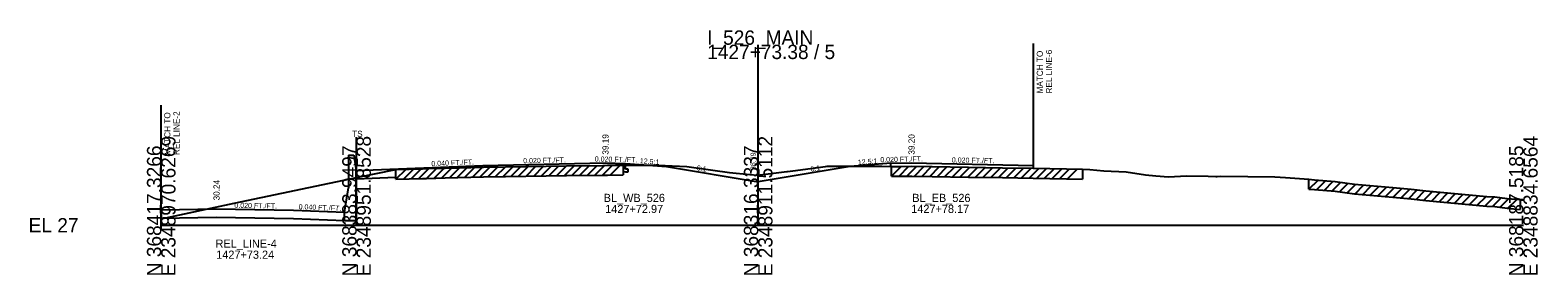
# Model space of a CAD drawing. Extents: x -170 to 2527928, y -10 to 1619750.
# Drawn here: x 3974.3 to 4269.9, y 5490.3 to 5538.2 of the extents above; entities that cross this region are included whole.
import ezdxf

# ---------------------------------------------------------------- set-up
doc = ezdxf.new("R2010")
doc.units = 0
for name, color, linetype in [('RD_GPK_XS_Cell', 7, 'Continuous'), ('RD_PD_NOISE-WALL-GM', 7, 'Continuous'), ('RD_XS_Base', 7, 'Continuous'), ('RD_XS_EarthShd', 7, 'Continuous'), ('RD_XS_ExGround', 7, 'Continuous'), ('RD_XS_ExPaveRet', 7, 'Continuous'), ('RD_XS_MatchLine', 7, 'Continuous'), ('RD_XS_Pave', 7, 'Continuous'), ('RD_XS_PaveShd', 7, 'Continuous'), ('RD_XS_TieSlope', 7, 'Continuous'), ('RD_XS_TX_Elev_EX', 7, 'Continuous'), ('RD_XS_TX_Slope', 7, 'Continuous'), ('RD_XS_TX_Station', 7, 'Continuous')]:
    doc.layers.add(name, color=color, linetype=linetype)

msp = doc.modelspace()

# ---------------------------------------------------------------- linework, layer by layer
at = {"layer": 'RD_GPK_XS_Cell'}
for p, q in [((4117.03, 5500), (4117.03, 5535.32)), ((4000, 5500), (4038.29, 5500)), ((4038.29, 5500), (4117.03, 5500)), ((4117.03, 5500), (4267.03, 5500))]:
    msp.add_line(p, q, dxfattribs=at)
at = {"layer": 'RD_PD_NOISE-WALL-GM'}
for p, q in [((4036.73, 5513.72), (4037.73, 5513.72)), ((4036.73, 5513.72), (4036.73, 5507.35)), ((4037.73, 5513.72), (4038.21, 5510.72)), ((4038.21, 5500.9), (4038.21, 5510.72)), ((4035.96, 5502.54), (4036.73, 5507.35)), ((4035.96, 5500.9), (4035.96, 5502.54)), ((4035.96, 5500.9), (4038.29, 5500.9))]:
    msp.add_line(p, q, dxfattribs=at)
at = {"layer": 'RD_XS_Base'}
for p, q in [((4038.21, 5509.08), (4046.02, 5509.4)), ((4046.02, 5510.94), (4046.02, 5511.03)), ((4090.54, 5510.49), (4091.03, 5510.48)), ((4091.03, 5510.98), (4091.03, 5512.11)), ((4091.53, 5510.97), (4091.03, 5510.98)), ((4091.03, 5510.48), (4091.53, 5510.47)), ((4091.53, 5510.47), (4091.53, 5510.97)), ((4143.03, 5511.5), (4143.03, 5512.12)), ((4171.03, 5511.14), (4171.03, 5511.72)), ((4000, 5501.39), (4010.78, 5501.6)), ((4010.78, 5501.6), (4025.96, 5501.3)), ((4025.96, 5501.3), (4035.96, 5500.9))]:
    msp.add_line(p, q, dxfattribs=at)
at = {"layer": 'RD_XS_EarthShd'}
for p, q in [((4091.03, 5512.11), (4099.03, 5511.47)), ((4143.03, 5512.12), (4135.03, 5511.48))]:
    msp.add_line(p, q, dxfattribs=at)
at = {"layer": 'RD_XS_ExGround'}
msp.add_lwpolyline([(4000, 5501.24), (4014.33, 5504.31), (4038.29, 5509.32), (4046.02, 5510.94), (4051.25, 5511.06), (4052.01, 5511.08), (4055.67, 5511.19), (4063.19, 5511.39), (4067.46, 5511.46), (4075.49, 5511.58), (4079.43, 5511.63), (4086.55, 5511.72), (4087.52, 5511.74), (4090.54, 5511.77), (4097.39, 5511.77), (4100.17, 5511.65), (4103.02, 5511.5), (4104.4, 5511.31), (4111.41, 5510.3), (4115.38, 5509.93), (4116.88, 5509.77), (4122.63, 5510.51), (4122.76, 5510.53), (4123.85, 5510.67), (4130.24, 5511.5), (4130.53, 5511.53), (4141.24, 5511.57), (4143.15, 5511.5), (4144.73, 5511.52), (4147.14, 5511.54), (4151.11, 5511.47), (4158.23, 5511.34), (4164.94, 5511.24), (4170.93, 5511.14), (4177.49, 5511.03), (4180.58, 5510.97), (4182.03, 5510.88), (4184.8, 5510.66), (4189.17, 5510.47), (4192.98, 5509.89), (4194.95, 5509.65), (4197.44, 5509.5), (4200.99, 5509.66), (4205.22, 5509.61), (4206.76, 5509.54), (4207.01, 5509.53), (4207.75, 5509.59), (4218.28, 5509.45), (4220.38, 5509.32), (4225, 5508.99), (4226.06, 5508.91), (4230.17, 5508.57), (4233.93, 5508.04), (4241.45, 5507.39), (4245.02, 5507.06), (4247.91, 5506.76), (4259.84, 5505.64), (4261.47, 5505.56), (4263.88, 5505.26), (4266.39, 5505.01), (4266.59, 5504.99), (4266.89, 5504.97), (4267.03, 5504.95)], dxfattribs=at)
at = {"layer": 'RD_XS_ExPaveRet'}
for p, q in [((4046.02, 5509.02), (4047.99, 5510.98)), ((4046.02, 5509.02), (4046.02, 5510.94)), ((4047.52, 5509.05), (4049.49, 5511.02)), ((4049.02, 5509.09), (4050.99, 5511.05)), ((4050.52, 5509.13), (4052.49, 5511.1)), ((4052.02, 5509.16), (4054, 5511.14)), ((4053.52, 5509.21), (4055.5, 5511.18)), ((4055.02, 5509.25), (4057, 5511.22)), ((4055.67, 5509.27), (4063.19, 5509.48)), ((4056.52, 5509.29), (4058.5, 5511.26)), ((4058.02, 5509.33), (4060, 5511.31)), ((4059.52, 5509.38), (4061.5, 5511.35)), ((4061.02, 5509.42), (4063, 5511.39)), ((4062.52, 5509.46), (4064.48, 5511.41)), ((4063.19, 5509.48), (4067.46, 5509.54)), ((4064.02, 5509.49), (4065.97, 5511.44)), ((4065.52, 5509.51), (4067.47, 5511.46)), ((4067.02, 5509.53), (4068.97, 5511.48)), ((4067.46, 5509.54), (4075.49, 5509.67)), ((4068.52, 5509.56), (4070.47, 5511.5)), ((4070.02, 5509.58), (4071.97, 5511.53)), ((4071.52, 5509.6), (4073.47, 5511.55)), ((4073.02, 5509.63), (4074.97, 5511.58)), ((4074.52, 5509.65), (4076.47, 5511.59)), ((4075.49, 5509.67), (4079.43, 5509.71)), ((4076.02, 5509.67), (4077.96, 5511.61)), ((4077.52, 5509.69), (4079.46, 5511.63)), ((4079.02, 5509.7), (4080.97, 5511.65)), ((4079.43, 5509.71), (4086.55, 5509.81)), ((4080.52, 5509.72), (4082.47, 5511.67)), ((4082.02, 5509.74), (4083.97, 5511.69)), ((4083.52, 5509.76), (4085.47, 5511.71)), ((4085.02, 5509.78), (4086.97, 5511.73)), ((4086.52, 5509.8), (4088.47, 5511.75)), ((4086.55, 5509.81), (4087.52, 5509.82)), ((4087.52, 5509.82), (4090.54, 5509.86)), ((4088.02, 5509.82), (4089.97, 5511.77)), ((4090.54, 5511.77), (4090.54, 5509.86)), ((4143.15, 5509.58), (4145.08, 5511.52)), ((4143.15, 5509.58), (4143.15, 5511.5)), ((4143.15, 5509.58), (4144.73, 5509.6)), ((4144.65, 5509.6), (4146.58, 5511.53)), ((4144.73, 5509.6), (4147.14, 5509.62)), ((4146.15, 5509.61), (4148.06, 5511.52)), ((4147.14, 5509.62), (4151.11, 5509.55)), ((4147.65, 5509.61), (4149.53, 5511.5)), ((4149.15, 5509.59), (4151.03, 5511.47)), ((4150.65, 5509.56), (4152.53, 5511.44)), ((4151.11, 5509.55), (4158.23, 5509.42)), ((4152.15, 5509.53), (4154.03, 5511.42)), ((4153.65, 5509.51), (4155.53, 5511.39)), ((4155.15, 5509.48), (4157.03, 5511.36)), ((4156.65, 5509.45), (4158.53, 5511.34)), ((4158.15, 5509.43), (4160.04, 5511.31)), ((4158.23, 5509.42), (4164.94, 5509.32)), ((4159.65, 5509.4), (4161.54, 5511.29)), ((4161.15, 5509.38), (4163.04, 5511.27)), ((4162.65, 5509.36), (4164.54, 5511.24)), ((4164.15, 5509.33), (4166.04, 5511.22)), ((4164.94, 5509.32), (4170.93, 5509.23)), ((4165.65, 5509.31), (4167.54, 5511.2)), ((4167.15, 5509.28), (4169.04, 5511.17)), ((4168.65, 5509.26), (4170.54, 5511.15)), ((4170.15, 5509.24), (4172.04, 5511.12)), ((4171.65, 5509.21), (4173.53, 5511.1)), ((4173.15, 5509.19), (4175.03, 5511.07)), ((4174.65, 5509.16), (4176.53, 5511.04)), ((4176.15, 5509.13), (4178.03, 5511.02)), ((4177.65, 5509.11), (4179.53, 5510.99)), ((4180.58, 5510.97), (4180.58, 5509.05)), ((4046.02, 5509.02), (4051.25, 5509.14)), ((4051.25, 5509.14), (4052.01, 5509.16)), ((4052.01, 5509.16), (4055.67, 5509.27)), ((4170.93, 5509.23), (4177.49, 5509.11)), ((4177.49, 5509.11), (4180.58, 5509.05)), ((4225, 5507.07), (4225, 5508.99)), ((4225, 5507.07), (4226.78, 5508.85)), ((4225, 5507.07), (4226.06, 5506.99)), ((4226.06, 5506.99), (4230.17, 5506.65)), ((4226.5, 5506.95), (4228.27, 5508.72)), ((4228, 5506.83), (4229.77, 5508.6)), ((4229.5, 5506.7), (4231.22, 5508.42)), ((4230.17, 5506.65), (4233.93, 5506.12)), ((4231, 5506.53), (4232.68, 5508.21)), ((4232.5, 5506.32), (4234.19, 5508.01)), ((4234, 5506.11), (4235.77, 5507.88)), ((4235.5, 5505.98), (4237.27, 5507.75)), ((4237, 5505.86), (4238.77, 5507.62)), ((4238.5, 5505.73), (4240.27, 5507.49)), ((4240, 5505.6), (4241.77, 5507.36)), ((4241.5, 5505.47), (4243.26, 5507.23)), ((4243, 5505.33), (4244.76, 5507.09)), ((4244.5, 5505.19), (4246.24, 5506.93)), ((4246, 5505.04), (4247.73, 5506.78)), ((4247.5, 5504.88), (4249.25, 5506.63)), ((4249, 5504.74), (4250.75, 5506.49)), ((4250.5, 5504.6), (4252.25, 5506.35)), ((4233.93, 5506.12), (4241.45, 5505.48)), ((4241.45, 5505.48), (4245.02, 5505.15)), ((4245.02, 5505.15), (4247.91, 5504.84)), ((4247.91, 5504.84), (4259.84, 5503.73)), ((4252, 5504.46), (4253.75, 5506.21)), ((4253.5, 5504.32), (4255.25, 5506.07)), ((4255, 5504.18), (4256.75, 5505.93)), ((4256.5, 5504.04), (4258.25, 5505.79)), ((4258, 5503.9), (4259.75, 5505.65)), ((4259.5, 5503.76), (4261.31, 5505.57)), ((4259.84, 5503.73), (4261.47, 5503.64)), ((4261, 5503.67), (4262.74, 5505.4)), ((4261.47, 5503.64), (4263.88, 5503.34)), ((4262.5, 5503.51), (4264.21, 5505.22)), ((4264, 5503.33), (4265.74, 5505.07)), ((4266.39, 5505.01), (4266.39, 5503.09)), ((4263.88, 5503.34), (4266.39, 5503.09))]:
    msp.add_line(p, q, dxfattribs=at)
at = {"layer": 'RD_XS_MatchLine'}
for p, q in [((4171.03, 5511.14), (4171.03, 5535.55)), ((4000, 5499.09), (4000, 5523.5)), ((4038.29, 5500), (4038.29, 5517.22))]:
    msp.add_line(p, q, dxfattribs=at)
at = {"layer": 'RD_XS_Pave'}
for p, q in [((4063.03, 5511.71), (4087.03, 5512.19)), ((4147.03, 5512.2), (4171.03, 5511.72)), ((4010.78, 5503.24), (4025.96, 5502.94))]:
    msp.add_line(p, q, dxfattribs=at)
at = {"layer": 'RD_XS_PaveShd'}
for p, q in [((4038.21, 5510.72), (4063.03, 5511.71)), ((4087.03, 5512.19), (4091.03, 5512.11)), ((4143.03, 5512.12), (4147.03, 5512.2)), ((4000, 5503.02), (4010.78, 5503.24)), ((4000, 5503.02), (4000, 5501.24)), ((4025.96, 5502.94), (4035.96, 5502.54))]:
    msp.add_line(p, q, dxfattribs=at)
at = {"layer": 'RD_XS_TieSlope'}
for p in [(4099.03, 5511.47), (4135.03, 5511.48)]:
    msp.add_line(p, (4117.03, 5508.48), dxfattribs=at)

# ---------------------------------------------------------------- texts
at = {"layer": 'RD_GPK_XS_Cell'}
for s, p in [('I_526_MAIN', (4107.03, 5535.32)), ('1427+73.38 / 5', (4107.03, 5532.52)), ('EL 27', (3974, 5498.6))]:
    msp.add_text(s, height=2.8, dxfattribs=at).set_placement(p)
for s, p in [('N 368417.3266', (4000, 5490)), ('E 2348970.6269', (4002.8, 5490)), ('N 368383.9497', (4038.29, 5490)), ('E 2348951.8528', (4041.09, 5490)), ('N 368316.3337', (4117.03, 5490)), ('E 2348911.5112', (4119.83, 5490)), ('N 368187.5185', (4267.03, 5490)), ('E 2348834.6564', (4269.83, 5490))]:
    msp.add_text(s, height=2.8, rotation=90, dxfattribs=at).set_placement(p)
at = {"layer": 'RD_XS_MatchLine'}
msp.add_text('TS', height=1.2, dxfattribs=at).set_placement((4037.44, 5517.28))
at = {"layer": 'RD_XS_TX_Elev_EX'}
msp.add_text('36.79', height=1, rotation=90, dxfattribs=at).set_placement((4116.53, 5510.79))
at = {"layer": 'RD_XS_TX_Slope'}
for s, rotation, p in [('0.040 FT./FT.', 2.2906, (4052.97, 5511.56)), ('0.020 FT./FT.', 1.1458, (4070.97, 5512.12)), ('0.020 FT./FT.', 358.8542, (4084.98, 5512.48)), ('12.5:1', 355.4261, (4093.79, 5512.15)), ('12.5:1', 4.5739, (4136.61, 5511.81)), ('0.020 FT./FT.', 1.1458, (4140.97, 5512.33)), ('0.020 FT./FT.', 358.8542, (4154.98, 5512.29)), ('6:1', 350.5377, (4104.9, 5510.78)), ('6:1', 9.4623, (4127.36, 5510.48)), ('0.020 FT./FT.', 358.8542, (4014.33, 5503.42)), ('0.040 FT./FT.', 357.7094, (4026.92, 5503.15))]:
    msp.add_text(s, height=1, rotation=rotation, dxfattribs=at).set_placement(p)
at = {"layer": 'RD_XS_TX_Station'}
for s, p in [('MATCH TO', (4172.84, 5525.78)), ('REL LINE-6', (4174.64, 5525.78)), ('MATCH TO', (4001.8, 5513.73)), ('REL LINE-2', (4003.6, 5513.73)), (' 39.19', (4087.69, 5513.37)), (' 39.20', (4147.69, 5513.37)), (' 30.24', (4011.44, 5504.41))]:
    msp.add_text(s, height=1.2, rotation=90, dxfattribs=at).set_placement(p)
for s, p in [('BL_WB_526', (4086.74, 5504.55)), ('1427+72.97', (4087.03, 5502.39)), ('1427+78.17', (4147.03, 5502.4)), ('BL_EB_526', (4147.23, 5504.55)), ('REL_LINE-4', (4010.65, 5495.61)), ('1427+73.24', (4010.78, 5493.44))]:
    msp.add_text(s, height=1.6, dxfattribs=at).set_placement(p)

doc.saveas('drawing.dxf')
